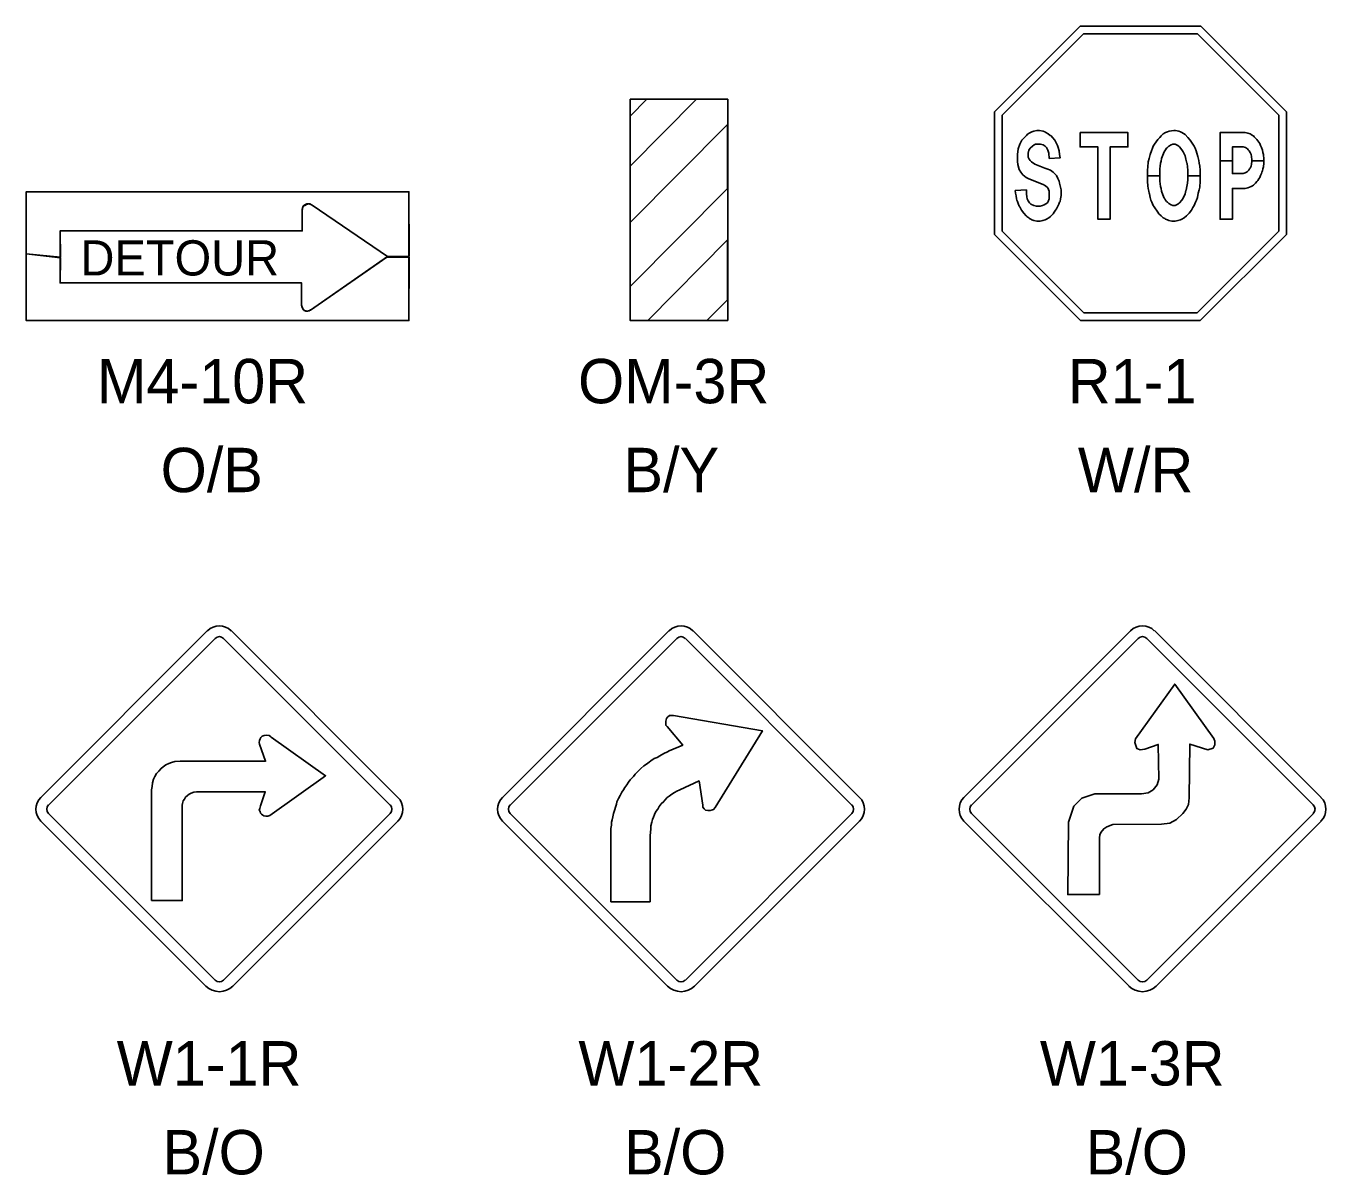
# Model space of a CAD drawing. Extents: x 10000 to 10794, y 10000 to 10499.
# Drawn here: x 10398.1 to 10500.6, y 10408.8 to 10499.4 of the extents above; entities that cross this region are included whole.
import ezdxf

# ---------------------------------------------------------------- set-up
doc = ezdxf.new("R2010")
doc.units = 0
doc.layers.add('DSIndex', color=7, linetype='Continuous')

msp = doc.modelspace()

# ---------------------------------------------------------------- linework, layer by layer
at = {"layer": 'DSIndex'}
for p, q in [((10474.44, 10492.61), (10481.21, 10499.38)), ((10481.21, 10499.38), (10490.71, 10499.38)), ((10497.48, 10492.61), (10490.71, 10499.38)), ((10475.05, 10492.36), (10481.46, 10498.77)), ((10481.46, 10498.77), (10490.45, 10498.77)), ((10496.87, 10492.36), (10490.45, 10498.77)), ((10474.44, 10482.94), (10474.44, 10492.61)), ((10474.44, 10492.6), (10474.44, 10492.61)), ((10475.05, 10483.2), (10475.05, 10492.36)), ((10496.87, 10483.2), (10496.87, 10492.36)), ((10497.48, 10482.94), (10497.48, 10492.61)), ((10497.48, 10492.6), (10497.48, 10492.61)), ((10493.21, 10488.75), (10492.24, 10488.75)), ((10492.24, 10488.75), (10493.21, 10488.75)), ((10495.68, 10488.75), (10494.75, 10488.75)), ((10494.75, 10488.75), (10495.68, 10488.75)), ((10486.51, 10487.56), (10487.48, 10487.56)), ((10487.48, 10487.56), (10486.51, 10487.56)), ((10489.7, 10487.56), (10490.66, 10487.56)), ((10490.66, 10487.56), (10489.7, 10487.56)), ((10398.11, 10486.31), (10398.11, 10476.15)), ((10428.28, 10486.31), (10398.11, 10486.31)), ((10428.28, 10476.15), (10428.28, 10486.31)), ((10426.59, 10481.2), (10420.66, 10485.25)), ((10419.88, 10483.22), (10419.88, 10484.92)), ((10419.88, 10483.22), (10400.78, 10483.22)), ((10400.78, 10479.12), (10400.78, 10483.22)), ((10481.24, 10476.15), (10474.44, 10482.94)), ((10481.49, 10476.76), (10475.05, 10483.2)), ((10490.43, 10476.76), (10496.87, 10483.2)), ((10490.68, 10476.15), (10497.48, 10482.94)), ((10426.59, 10481.2), (10420.53, 10476.98)), ((10419.82, 10479.12), (10400.78, 10479.12)), ((10419.82, 10479.12), (10419.82, 10477.36)), ((10490.43, 10476.76), (10481.49, 10476.76)), ((10398.11, 10476.15), (10428.28, 10476.15)), ((10490.68, 10476.15), (10481.24, 10476.15)), ((10399.26, 10438.55), (10412.41, 10451.7)), ((10414.28, 10451.7), (10427.42, 10438.55)), ((10435.66, 10438.55), (10448.8, 10451.7)), ((10450.67, 10451.7), (10463.82, 10438.55)), ((10472.04, 10438.55), (10485.19, 10451.7)), ((10487.06, 10451.7), (10500.2, 10438.55)), ((10399.87, 10437.95), (10413, 10451.08)), ((10413.68, 10451.08), (10426.81, 10437.95)), ((10436.27, 10437.95), (10449.4, 10451.08)), ((10450.08, 10451.08), (10463.21, 10437.95)), ((10472.65, 10437.95), (10485.78, 10451.08)), ((10486.46, 10451.08), (10499.59, 10437.95)), ((10413, 10424.15), (10399.87, 10437.28)), ((10426.81, 10437.28), (10413.68, 10424.15)), ((10449.4, 10424.15), (10436.27, 10437.28)), ((10463.21, 10437.28), (10450.08, 10424.15)), ((10485.78, 10424.15), (10472.65, 10437.28)), ((10499.59, 10437.28), (10486.46, 10424.15)), ((10412.41, 10423.53), (10399.26, 10436.68)), ((10427.42, 10436.68), (10414.28, 10423.53)), ((10448.8, 10423.53), (10435.66, 10436.68)), ((10463.82, 10436.68), (10450.67, 10423.53)), ((10485.19, 10423.53), (10472.04, 10436.68)), ((10500.2, 10436.68), (10487.06, 10423.53))]:
    msp.add_line(p, q, dxfattribs=at)
for points in [[(10453.42, 10476.15), (10445.73, 10476.15), (10445.73, 10493.61), (10453.42, 10493.61)], [(10447.05, 10493.61), (10445.73, 10492.27), (10445.73, 10488.33), (10450.95, 10493.61)], [(10445.73, 10478.84), (10453.39, 10486.58), (10453.39, 10491.62), (10445.73, 10483.88)], [(10426.59, 10481.2), (10428.3, 10481.23), (10428.28, 10486.31), (10398.11, 10486.31), (10398.1, 10481.42), (10400.81, 10481.16), (10400.78, 10483.22), (10419.88, 10483.22), (10419.88, 10484.92), (10419.96, 10485.17), (10420.09, 10485.24), (10420.22, 10485.3), (10420.41, 10485.37), (10420.66, 10485.25)], [(10447.11, 10476.16), (10453.39, 10482.51), (10453.39, 10477.79), (10451.78, 10476.16)], [(10426.55, 10481.16), (10428.3, 10481.16), (10428.28, 10476.15), (10398.11, 10476.15), (10398.1, 10481.42), (10400.81, 10481.1), (10400.78, 10479.12), (10419.82, 10479.12), (10419.82, 10477.36), (10419.89, 10477.15), (10419.96, 10477.02), (10420.02, 10476.96), (10420.15, 10476.89), (10420.28, 10476.89), (10420.53, 10476.98)], [(10482.72, 10430.89), (10482.72, 10435.37), (10482.75, 10435.6), (10482.84, 10435.79), (10483.07, 10436.08), (10483.31, 10436.23), (10483.79, 10436.41), (10487.61, 10436.45), (10488.27, 10436.53), (10488.8, 10436.8), (10489.29, 10437.28), (10489.56, 10437.62), (10489.74, 10438), (10489.79, 10438.52), (10489.84, 10442.75), (10491.28, 10442.29), (10491.68, 10442.43), (10491.82, 10442.69), (10491.82, 10442.99), (10491.75, 10443.19), (10488.67, 10447.49), (10485.56, 10443.17), (10485.51, 10442.87), (10485.67, 10442.41), (10485.93, 10442.29), (10486.3, 10442.36), (10487.36, 10442.73), (10487.42, 10439.99), (10487.29, 10439.54), (10486.96, 10439.14), (10486.57, 10438.91), (10486.04, 10438.84), (10482.36, 10438.84), (10481.35, 10438.5), (10480.71, 10437.86), (10480.29, 10436.59), (10480.23, 10430.89)], [(10444.2, 10430.32), (10444.2, 10435.53), (10444.21, 10435.79), (10444.21, 10436.09), (10444.25, 10436.37), (10444.26, 10436.6), (10444.3, 10436.78), (10444.37, 10437.03), (10444.41, 10437.27), (10444.52, 10437.59), (10444.57, 10437.79), (10444.64, 10438.02), (10444.69, 10438.19), (10444.82, 10438.47), (10444.94, 10438.71), (10445.08, 10438.97), (10445.21, 10439.16), (10445.3, 10439.33), (10445.46, 10439.55), (10445.61, 10439.76), (10445.73, 10439.93), (10445.82, 10440.02), (10445.98, 10440.2), (10446.13, 10440.37), (10446.29, 10440.53), (10446.44, 10440.69), (10446.58, 10440.84), (10446.81, 10441.05), (10447.02, 10441.18), (10447.22, 10441.33), (10447.36, 10441.44), (10447.62, 10441.61), (10447.86, 10441.71), (10448.07, 10441.84), (10448.37, 10442), (10448.68, 10442.14), (10448.81, 10442.21), (10449.88, 10442.67), (10448.64, 10444.14), (10448.54, 10444.24), (10448.53, 10444.41), (10448.53, 10444.57), (10448.59, 10444.76), (10448.68, 10444.88), (10448.83, 10445), (10449.14, 10445), (10456.15, 10443.81), (10452.43, 10437.75), (10452.31, 10437.6), (10452.23, 10437.56), (10452.04, 10437.51), (10451.87, 10437.51), (10451.67, 10437.55), (10451.55, 10437.65), (10451.45, 10437.78), (10451.45, 10437.95), (10451.16, 10439.85), (10449.64, 10439.16), (10449.41, 10439.05), (10449.23, 10438.93), (10449.01, 10438.8), (10448.81, 10438.65), (10448.64, 10438.53), (10448.45, 10438.34), (10448.37, 10438.24), (10448.18, 10438.04), (10448.01, 10437.83), (10447.9, 10437.62), (10447.76, 10437.43), (10447.66, 10437.2), (10447.58, 10437), (10447.5, 10436.8), (10447.44, 10436.59), (10447.35, 10436.32), (10447.36, 10436.07), (10447.3, 10435.53), (10447.3, 10430.32)], [(10408, 10430.41), (10408, 10439.14), (10408.04, 10439.41), (10408.07, 10439.71), (10408.15, 10439.98), (10408.26, 10440.2), (10408.39, 10440.43), (10408.56, 10440.62), (10408.74, 10440.84), (10408.91, 10440.97), (10409.13, 10441.11), (10409.36, 10441.23), (10409.57, 10441.3), (10409.82, 10441.38), (10410.26, 10441.4), (10416.99, 10441.4), (10416.51, 10442.74), (10416.48, 10442.89), (10416.51, 10443.04), (10416.55, 10443.17), (10416.62, 10443.27), (10416.72, 10443.38), (10416.88, 10443.44), (10417.07, 10443.45), (10417.26, 10443.42), (10417.36, 10443.36), (10417.43, 10443.31), (10421.72, 10440.26), (10417.31, 10437.11), (10417.17, 10437.08), (10417.01, 10437.06), (10416.86, 10437.1), (10416.76, 10437.14), (10416.67, 10437.23), (10416.58, 10437.32), (10416.55, 10437.43), (10416.49, 10437.54), (10416.53, 10437.68), (10416.58, 10437.88), (10416.96, 10438.99), (10411.54, 10438.99), (10411.33, 10438.95), (10411.11, 10438.89), (10410.96, 10438.81), (10410.82, 10438.71), (10410.68, 10438.57), (10410.58, 10438.42), (10410.49, 10438.27), (10410.44, 10438.07), (10410.41, 10437.94), (10410.41, 10437.86), (10410.41, 10430.41)]]:
    msp.add_lwpolyline(points, close=True, dxfattribs=at)
for points in [[(10479.02, 10490.6), (10478.91, 10490.71), (10478.84, 10490.76), (10478.69, 10490.87), (10478.51, 10490.98), (10478.41, 10491.03), (10478.3, 10491.08), (10478.01, 10491.14), (10477.87, 10491.14), (10477.8, 10491.14), (10477.55, 10491.08), (10477.4, 10491.03), (10477.19, 10490.92), (10477.04, 10490.82), (10476.97, 10490.76), (10476.87, 10490.65), (10476.76, 10490.55)], [(10488.59, 10491.14), (10488.23, 10491.08), (10488.08, 10491.03), (10487.94, 10490.98), (10487.76, 10490.87), (10487.69, 10490.82), (10487.58, 10490.71), (10487.48, 10490.6), (10487.37, 10490.49), (10487.33, 10490.44), (10487.08, 10490.06), (10486.97, 10489.9), (10486.9, 10489.74), (10486.83, 10489.53), (10486.72, 10489.26), (10486.65, 10488.93), (10486.58, 10488.67), (10486.57, 10488.6)], [(10490.66, 10487.56), (10490.66, 10487.86), (10490.66, 10488.02), (10490.63, 10488.34), (10490.59, 10488.56), (10490.56, 10488.77), (10490.49, 10489.1), (10490.41, 10489.36), (10490.34, 10489.53), (10490.27, 10489.74), (10490.2, 10489.9), (10490.09, 10490.06), (10489.88, 10490.39), (10489.7, 10490.6), (10489.48, 10490.82), (10489.23, 10490.98), (10489.12, 10491.03), (10488.98, 10491.08), (10488.73, 10491.14), (10488.59, 10491.14)], [(10476.76, 10490.55), (10476.62, 10490.39), (10476.44, 10490.06), (10476.33, 10489.69), (10476.26, 10489.26), (10476.26, 10488.77), (10476.26, 10488.7)], [(10477.12, 10489.2), (10477.12, 10489.36), (10477.15, 10489.58), (10477.26, 10489.74), (10477.44, 10489.9), (10477.58, 10490.01), (10477.69, 10490.06), (10477.87, 10490.06), (10478.08, 10490.06), (10478.3, 10490.01), (10478.44, 10489.9), (10478.55, 10489.79), (10478.66, 10489.58), (10478.73, 10489.36), (10478.76, 10488.93)], [(10478.76, 10488.93), (10479.63, 10488.99), (10479.59, 10489.26), (10479.55, 10489.53), (10479.48, 10489.79), (10479.41, 10489.96), (10479.3, 10490.22), (10479.2, 10490.39), (10479.02, 10490.6)], [(10482.6, 10486), (10482.6, 10484.15), (10483.57, 10484.15), (10483.57, 10489.85), (10484.97, 10489.85), (10484.97, 10490.98), (10481.2, 10490.98)], [(10481.2, 10490.98), (10481.2, 10489.85), (10482.6, 10489.85), (10482.6, 10489.55)], [(10487.48, 10487.64), (10487.48, 10487.75), (10487.48, 10487.97), (10487.48, 10488.13), (10487.51, 10488.34), (10487.55, 10488.56), (10487.58, 10488.72), (10487.62, 10488.93), (10487.73, 10489.2), (10487.83, 10489.47), (10487.87, 10489.53), (10487.94, 10489.63), (10488.01, 10489.74), (10488.08, 10489.79), (10488.19, 10489.9), (10488.37, 10490.01), (10488.52, 10490.06), (10488.62, 10490.06), (10488.69, 10490.06), (10488.8, 10490.01), (10488.91, 10489.96), (10489.05, 10489.85), (10489.23, 10489.63), (10489.34, 10489.47), (10489.48, 10489.15), (10489.55, 10488.88), (10489.62, 10488.56), (10489.63, 10488.53)], [(10494.21, 10490.98), (10492.24, 10490.98), (10492.24, 10489.94)], [(10495.68, 10488.75), (10495.68, 10488.93), (10495.65, 10489.2), (10495.65, 10489.26), (10495.61, 10489.42), (10495.58, 10489.58), (10495.5, 10489.79), (10495.43, 10489.96), (10495.36, 10490.12), (10495.29, 10490.22), (10495.22, 10490.33), (10495.14, 10490.44), (10495.04, 10490.55), (10494.93, 10490.65), (10494.86, 10490.71), (10494.79, 10490.76), (10494.68, 10490.82), (10494.61, 10490.87), (10494.43, 10490.92), (10494.21, 10490.98)], [(10479.59, 10485.49), (10479.63, 10485.55), (10479.66, 10485.76), (10479.7, 10486.03), (10479.7, 10486.3), (10479.7, 10486.46), (10479.66, 10486.68), (10479.59, 10487), (10479.55, 10487.16), (10479.45, 10487.37), (10479.34, 10487.59), (10479.23, 10487.7), (10479.09, 10487.86), (10478.87, 10488.02), (10478.59, 10488.13), (10478.41, 10488.18), (10477.62, 10488.5), (10477.37, 10488.67), (10477.26, 10488.77), (10477.19, 10488.88), (10477.12, 10489.04), (10477.12, 10489.2)], [(10482.6, 10489.55), (10482.6, 10486)], [(10492.24, 10489.94), (10492.24, 10489.2)], [(10492.24, 10489.2), (10492.24, 10488.75)], [(10493.21, 10488.75), (10493.21, 10489.85), (10494, 10489.85)], [(10494, 10489.85), (10494.03, 10489.85), (10494.07, 10489.85), (10494.25, 10489.79), (10494.32, 10489.74), (10494.39, 10489.69), (10494.46, 10489.63), (10494.54, 10489.53), (10494.61, 10489.42), (10494.68, 10489.26), (10494.71, 10489.1), (10494.75, 10488.83), (10494.75, 10488.75)], [(10476.26, 10488.7), (10476.29, 10488.45), (10476.4, 10488.07), (10476.54, 10487.86), (10476.69, 10487.64), (10476.94, 10487.43), (10477.15, 10487.32), (10478.3, 10486.89), (10478.48, 10486.78), (10478.66, 10486.62), (10478.76, 10486.35), (10478.76, 10486.08), (10478.76, 10485.92)], [(10486.57, 10488.6), (10486.54, 10488.34), (10486.51, 10487.97), (10486.51, 10487.7), (10486.51, 10487.56)], [(10489.63, 10488.53), (10489.66, 10488.29), (10489.7, 10488.02), (10489.7, 10487.75), (10489.7, 10487.64)], [(10492.24, 10488.75), (10492.24, 10486.7)], [(10494, 10487.75), (10493.21, 10487.75), (10493.21, 10488.75)], [(10494.75, 10488.75), (10494.75, 10488.72), (10494.71, 10488.5), (10494.68, 10488.34), (10494.61, 10488.18), (10494.57, 10488.13), (10494.5, 10488.02), (10494.39, 10487.91), (10494.32, 10487.86), (10494.21, 10487.8), (10494.07, 10487.75), (10494, 10487.75)], [(10494.21, 10486.57), (10494.43, 10486.62), (10494.57, 10486.68), (10494.68, 10486.73), (10494.79, 10486.78), (10494.86, 10486.84), (10494.93, 10486.89), (10495.04, 10487), (10495.14, 10487.11), (10495.22, 10487.21), (10495.29, 10487.32), (10495.36, 10487.43), (10495.43, 10487.59), (10495.5, 10487.75), (10495.54, 10487.86), (10495.58, 10487.97), (10495.61, 10488.13), (10495.65, 10488.29), (10495.68, 10488.56), (10495.68, 10488.72), (10495.68, 10488.75)], [(10486.51, 10487.56), (10486.51, 10487.37), (10486.51, 10487.11), (10486.54, 10486.78), (10486.58, 10486.57), (10486.62, 10486.35), (10486.65, 10486.19), (10486.66, 10486.15)], [(10486.66, 10486.15), (10486.72, 10485.87), (10486.79, 10485.65), (10486.87, 10485.49), (10486.97, 10485.22), (10487.05, 10485.12), (10487.33, 10484.69), (10487.4, 10484.58), (10487.58, 10484.42), (10487.69, 10484.31), (10487.76, 10484.26), (10487.87, 10484.2), (10487.94, 10484.15), (10488.08, 10484.1), (10488.19, 10484.04), (10488.44, 10483.99), (10488.62, 10483.99), (10488.69, 10483.99), (10488.91, 10484.04), (10489.12, 10484.1), (10489.23, 10484.15), (10489.41, 10484.26), (10489.59, 10484.42), (10489.7, 10484.53), (10489.8, 10484.63), (10489.98, 10484.85), (10490.09, 10485.06), (10490.2, 10485.22), (10490.31, 10485.49), (10490.38, 10485.65), (10490.45, 10485.87), (10490.52, 10486.19), (10490.59, 10486.46), (10490.63, 10486.68), (10490.66, 10487.16), (10490.66, 10487.54)], [(10487.48, 10487.56), (10487.48, 10487.64)], [(10488.62, 10485.22), (10488.52, 10485.22), (10488.37, 10485.28), (10488.19, 10485.39), (10488.08, 10485.49), (10488.01, 10485.55), (10487.94, 10485.65), (10487.87, 10485.76), (10487.83, 10485.82), (10487.73, 10486.08), (10487.62, 10486.35), (10487.58, 10486.57), (10487.55, 10486.73), (10487.51, 10486.94), (10487.48, 10487.16), (10487.48, 10487.32), (10487.48, 10487.54), (10487.48, 10487.56)], [(10489.7, 10487.56), (10489.7, 10487.54), (10489.7, 10487.27), (10489.66, 10487), (10489.62, 10486.73), (10489.56, 10486.43)], [(10489.7, 10487.64), (10489.7, 10487.56)], [(10490.66, 10487.54), (10490.66, 10487.56)], [(10476.97, 10486.3), (10476.97, 10486.46), (10476.08, 10486.41)], [(10476.08, 10486.41), (10476.11, 10486.19), (10476.15, 10485.98), (10476.19, 10485.76), (10476.22, 10485.65), (10476.26, 10485.55), (10476.33, 10485.39), (10476.4, 10485.17), (10476.44, 10485.12), (10476.58, 10484.85), (10476.76, 10484.63), (10476.94, 10484.42), (10477.01, 10484.36), (10477.15, 10484.26), (10477.22, 10484.2), (10477.33, 10484.15), (10477.4, 10484.1), (10477.55, 10484.04), (10477.8, 10483.99), (10477.91, 10483.99), (10478.01, 10483.99), (10478.05, 10484)], [(10478.37, 10485.28), (10478.23, 10485.22), (10478.05, 10485.17), (10477.87, 10485.17), (10477.76, 10485.17), (10477.55, 10485.22), (10477.33, 10485.33), (10477.22, 10485.44), (10477.12, 10485.6), (10477.04, 10485.76), (10477.01, 10485.92), (10476.97, 10486.14), (10476.97, 10486.3)], [(10489.56, 10486.43), (10489.55, 10486.41), (10489.48, 10486.14), (10489.34, 10485.82), (10489.23, 10485.65), (10489.05, 10485.44), (10488.91, 10485.33), (10488.8, 10485.28), (10488.69, 10485.22), (10488.62, 10485.22)], [(10492.24, 10486.7), (10492.24, 10484.15), (10493.21, 10484.15), (10493.21, 10486.57), (10493.39, 10486.57)], [(10493.39, 10486.57), (10494.21, 10486.57)], [(10478.05, 10484), (10478.26, 10484.04), (10478.44, 10484.1), (10478.55, 10484.15), (10478.73, 10484.26), (10478.87, 10484.36), (10478.98, 10484.47), (10479.09, 10484.58), (10479.16, 10484.69), (10479.27, 10484.85), (10479.34, 10484.96), (10479.45, 10485.17), (10479.52, 10485.33), (10479.59, 10485.49)], [(10478.76, 10485.92), (10478.76, 10485.76), (10478.69, 10485.55), (10478.62, 10485.44), (10478.37, 10485.28)]]:
    msp.add_lwpolyline(points, dxfattribs=at)
for centre, radius, start, end in [((10420.34, 10484.92), 0.453, 55.6628, 180), ((10420.27, 10477.36), 0.453, 180, 304.8245), ((10413.34, 10450.76), 1.32, 45, 135), ((10413.34, 10450.75), 0.478, 45, 135), ((10449.74, 10450.76), 1.32, 45, 135), ((10449.74, 10450.75), 0.478, 45, 135), ((10486.12, 10450.76), 1.32, 45, 135), ((10486.12, 10450.75), 0.478, 45, 135), ((10400.2, 10437.62), 1.32, 135, 225), ((10400.21, 10437.62), 0.478, 135, 225), ((10426.47, 10437.62), 0.478, 315, 45), ((10426.48, 10437.62), 1.32, 315, 45), ((10436.6, 10437.62), 1.32, 135, 225), ((10436.61, 10437.62), 0.478, 135, 225), ((10462.87, 10437.62), 0.478, 315, 45), ((10462.88, 10437.62), 1.32, 315, 45), ((10472.98, 10437.62), 1.32, 135, 225), ((10472.99, 10437.62), 0.478, 135, 225), ((10499.25, 10437.62), 0.478, 315, 45), ((10499.26, 10437.62), 1.32, 315, 45), ((10413.34, 10424.75), 1.52, 225.2192, 314.7663), ((10413.34, 10424.48), 0.478, 225, 315), ((10449.74, 10424.75), 1.52, 225.2192, 314.7663), ((10449.74, 10424.48), 0.478, 225, 315), ((10486.12, 10424.75), 1.52, 225.2192, 314.7663), ((10486.12, 10424.48), 0.478, 225, 315)]:
    msp.add_arc(centre, radius, start, end, dxfattribs=at)

# ---------------------------------------------------------------- texts
for s, height, p in [('DETOUR', 2.774, (10402.39, 10479.71)), ('M4-10R', 3.5, (10403.69, 10469.63)), ('OM-3R', 3.5, (10441.62, 10469.63)), ('R1-1', 3.5, (10480.23, 10469.63)), ('O/B', 3.5, (10408.71, 10462.62)), ('B/Y', 3.5, (10445.2, 10462.62)), ('W/R', 3.5, (10481.03, 10462.62)), ('W1-2R', 3.5, (10441.65, 10415.83)), ('W1-3R', 3.5, (10478.03, 10415.83)), ('W1-1R', 3.5, (10405.25, 10415.83)), ('B/O', 3.5, (10408.86, 10408.82)), ('B/O', 3.5, (10445.25, 10408.82)), ('B/O', 3.5, (10481.64, 10408.82))]:
    msp.add_text(s, height=height, dxfattribs=at).set_placement(p)

doc.saveas('drawing.dxf')
